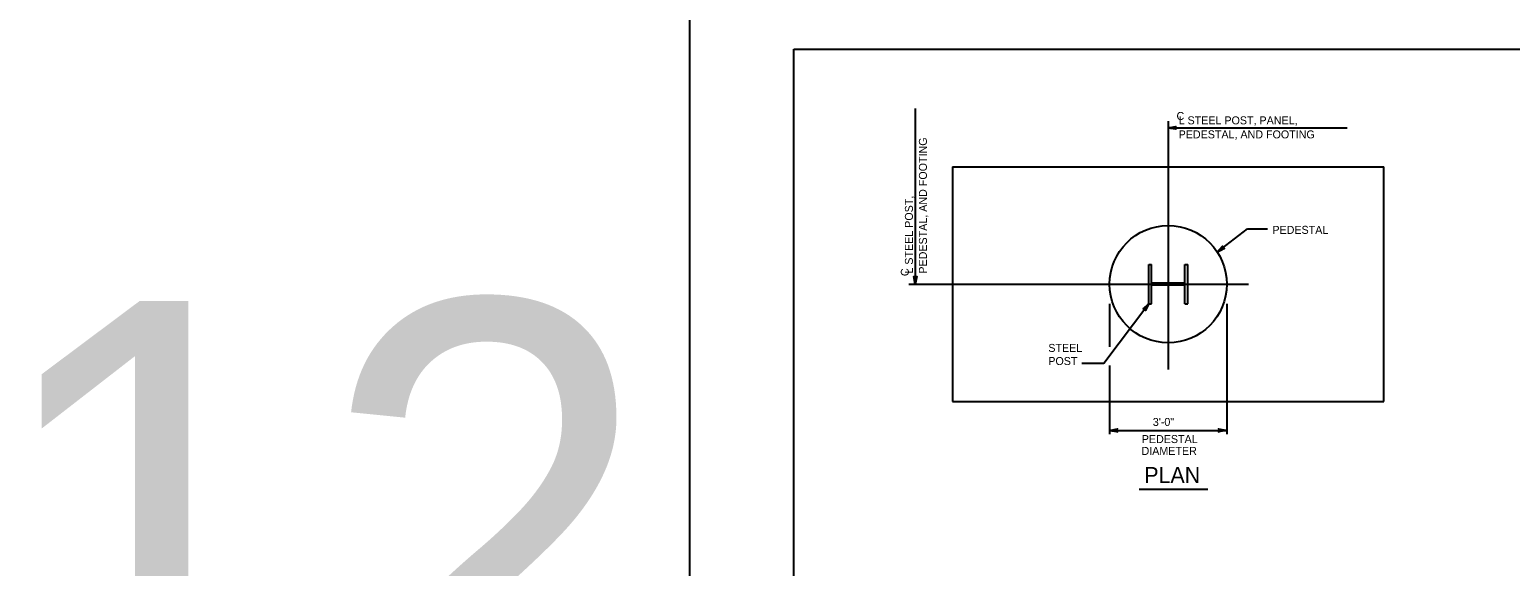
# Model space of a CAD drawing. Extents: x 3475 to 6558, y -3780 to 1166.
# Drawn here: x 3508 to 4076, y -2018 to -1812 of the extents above; entities that cross this region are included whole.
import ezdxf

# ---------------------------------------------------------------- set-up
doc = ezdxf.new("R2010")
doc.units = 0
for name, color, linetype in [('1', 7, 'Continuous'), ('2', 7, 'Continuous'), ('PLT-BNDY', 7, 'Continuous')]:
    doc.layers.add(name, color=color, linetype=linetype)

msp = doc.modelspace()

# ---------------------------------------------------------------- linework, layer by layer
at = {"layer": '1'}
for p, q in [((3847.96, -1842.13), (3847.96, -1909.53)), ((3945.07, -1846.91), (3945.07, -1942.32)), ((3945.07, -1849.51), (4013.75, -1849.51)), ((3862.28, -1864.52), (3862.28, -1954.53)), ((3862.28, -1864.52), (4027.86, -1864.52)), ((4027.86, -1954.53), (4027.86, -1864.52)), ((3963.91, -1897.21), (3975.47, -1888.31)), ((3975.47, -1888.31), (3983.2, -1888.31)), ((3937.57, -1917.03), (3937.57, -1902.02)), ((3937.57, -1902.02), (3938.7, -1902.03)), ((3938.7, -1909.09), (3938.7, -1902.03)), ((3951.45, -1902.03), (3952.57, -1902.03)), ((3951.45, -1909.09), (3951.45, -1902.03)), ((3952.57, -1917.03), (3952.57, -1902.03)), ((3845.51, -1909.53), (3975.85, -1909.53)), ((3951.45, -1909.09), (3938.7, -1909.09)), ((3951.45, -1909.96), (3938.7, -1909.96)), ((3938.7, -1917.03), (3938.7, -1909.96)), ((3951.44, -1917.03), (3951.45, -1909.96)), ((3922.57, -1917.07), (3922.57, -1933.6)), ((3937.57, -1917.03), (3938.7, -1917.03)), ((3951.45, -1917.03), (3952.57, -1917.03)), ((3967.57, -1917.07), (3967.57, -1967.13)), ((3922.57, -1940.73), (3922.57, -1967.13)), ((3862.28, -1954.53), (4027.86, -1954.53)), ((3922.57, -1965.68), (3967.38, -1965.68)), ((3933.93, -1988.2), (3960.25, -1988.2))]:
    msp.add_line(p, q, dxfattribs=at)
for points in [[(3945.07, -1849.51), (3948.05, -1848.95), (3947.82, -1849.11), (3947.71, -1849.31), (3947.67, -1849.51), (3947.71, -1849.71), (3947.82, -1849.91), (3948.05, -1850.07), (3945.07, -1849.51), (3947.82, -1849.91), (3947.71, -1849.71), (3945.07, -1849.51), (3947.67, -1849.51), (3947.71, -1849.31), (3945.07, -1849.51), (3947.82, -1849.11)], [(3963.91, -1897.21), (3965.93, -1894.95), (3965.89, -1895.08), (3965.84, -1895.22), (3965.86, -1895.33), (3965.87, -1895.45), (3965.92, -1895.54), (3965.97, -1895.63), (3966.04, -1895.7), (3966.12, -1895.77), (3966.22, -1895.81), (3966.33, -1895.85), (3966.47, -1895.85), (3966.61, -1895.84), (3963.91, -1897.21), (3966.47, -1895.85), (3966.33, -1895.85), (3963.91, -1897.21), (3966.22, -1895.81), (3966.12, -1895.77), (3963.91, -1897.21), (3966.04, -1895.7), (3965.97, -1895.63), (3963.91, -1897.21), (3965.92, -1895.54), (3965.87, -1895.45), (3963.91, -1897.21), (3965.86, -1895.33), (3965.84, -1895.22), (3963.91, -1897.21), (3965.89, -1895.08)], [(3847.96, -1909.53), (3847.4, -1906.54), (3847.56, -1906.77), (3847.76, -1906.89), (3847.96, -1906.93), (3848.16, -1906.89), (3848.36, -1906.77), (3848.52, -1906.54), (3847.96, -1909.53), (3848.36, -1906.77), (3848.16, -1906.89), (3847.96, -1909.53), (3847.96, -1906.93), (3847.76, -1906.89), (3847.96, -1909.53), (3847.56, -1906.77)], [(3911.94, -1939.85), (3920.3, -1939.85), (3937.63, -1916.89)], [(3937.63, -1916.89), (3936.28, -1919.61), (3936.3, -1919.33), (3936.21, -1919.11), (3936.07, -1918.97), (3935.89, -1918.87), (3935.66, -1918.85), (3935.39, -1918.93), (3937.63, -1916.89), (3935.66, -1918.85), (3935.89, -1918.87), (3937.63, -1916.89), (3936.07, -1918.97), (3936.21, -1919.11), (3937.63, -1916.89), (3936.3, -1919.33)], [(3922.57, -1965.68), (3925.55, -1965.12), (3925.32, -1965.28), (3925.21, -1965.48), (3925.17, -1965.68), (3925.21, -1965.88), (3925.32, -1966.08), (3925.55, -1966.24), (3922.57, -1965.68), (3925.32, -1966.08), (3925.21, -1965.88), (3922.57, -1965.68), (3925.17, -1965.68), (3925.21, -1965.48), (3922.57, -1965.68), (3925.32, -1965.28)], [(3967.38, -1965.68), (3964.4, -1966.24), (3964.63, -1966.08), (3964.75, -1965.88), (3964.78, -1965.68), (3964.75, -1965.48), (3964.63, -1965.28), (3964.4, -1965.12), (3967.38, -1965.68), (3964.63, -1965.28), (3964.75, -1965.48), (3967.38, -1965.68), (3964.78, -1965.68), (3964.75, -1965.88), (3967.38, -1965.68), (3964.63, -1966.08)]]:
    msp.add_lwpolyline(points, dxfattribs=at)
msp.add_circle((3945.07, -1909.53), 22.5, dxfattribs=at)
at = {"layer": '2'}
for p, q in [((3801.34, -2383.31), (3801.34, -1819.31)), ((3801.34, -1819.31), (4587.34, -1819.31))]:
    msp.add_line(p, q, dxfattribs=at)
at = {"layer": 'PLT-BNDY'}
msp.add_lwpolyline([(3761.34, -1804.31), (4602.34, -1804.31), (4602.34, -2398.31), (3761.34, -2398.31)], close=True, dxfattribs=at)

# ---------------------------------------------------------------- texts
at = {"layer": '1'}
for s, height, p in [('C', 3.07, (3948.26, -1846.49)), ('L STEEL POST, PANEL,', 3.072, (3949.06, -1848.18)), ('PEDESTAL, AND FOOTING', 3.072, (3949.06, -1853.56)), ('PEDESTAL', 3.072, (3985.07, -1890.21)), ('12', 172.802, (3490.29, -2088.82)), ('STEEL', 3.072, (3899.03, -1935.53)), ('POST', 3.072, (3899.03, -1940.57)), ('3\'-0"', 3.072, (3939.15, -1963.95)), ('DIAMETER', 3.072, (3934.82, -1975.07)), ('PEDESTAL', 3.072, (3934.91, -1970.52)), ('PLAN', 6.144, (3935.87, -1985.86))]:
    msp.add_text(s, height=height, dxfattribs=at).set_placement(p)
for s, height, p in [('PEDESTAL, AND FOOTING', 3.072, (3852.42, -1905.47)), ('L STEEL POST,', 3.072, (3847.04, -1905.47)), ('C', 3.07, (3845.48, -1906.43))]:
    msp.add_text(s, height=height, rotation=90, dxfattribs=at).set_placement(p)

doc.saveas('drawing.dxf')
